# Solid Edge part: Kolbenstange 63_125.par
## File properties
Username: ahadarics
Dokumentum tartalom típus: 0
Author: ahadarics
Last saved by: ahadarics
Revision: 82
Sűrűség: 0,000 kg/m^3
Pontosság: 0,990
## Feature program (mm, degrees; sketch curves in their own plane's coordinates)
base feature "unnamed BaseFeature 1"
thread "unnamed Thread 1"
chamfer "Letörés_1"  SetBackValue2 = 20 deg
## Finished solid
Body 1: solid body, 20 faces, 31 edges, 14 vertices.
  Faces by surface: plane 8, cylinder 5, torus 4, cone 3
  Edges by curve: circle 16, line 9, curve on surface 4, ellipse 2
Bounding box of the edges (mm; curved faces can reach further): 63.000 x 63.000 x 281.500, from (-31.5, -31.5, -70.75) to (31.5, 31.5, 210.75).
Cylindrical faces by radius (mm): R6.75 x1, R8 x1, R9.75 x1, R10 x1, R31.5 x1
Conical faces (half-angle, radius in mm at the cone's reference point): 20 deg R8 x1, 30 deg R9.875 x1, 60 deg R7.375 x1
Toroidal faces (ring radius, tube radius in mm): R7.15 r0.4 x2, R8.55 r1.2 x2
Planar faces by outward normal: +x 1, +z 3, -x 1, -z 1, oblique 2
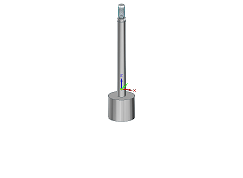
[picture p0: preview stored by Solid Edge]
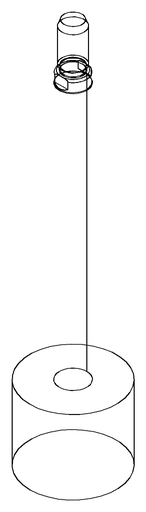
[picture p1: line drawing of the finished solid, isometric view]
